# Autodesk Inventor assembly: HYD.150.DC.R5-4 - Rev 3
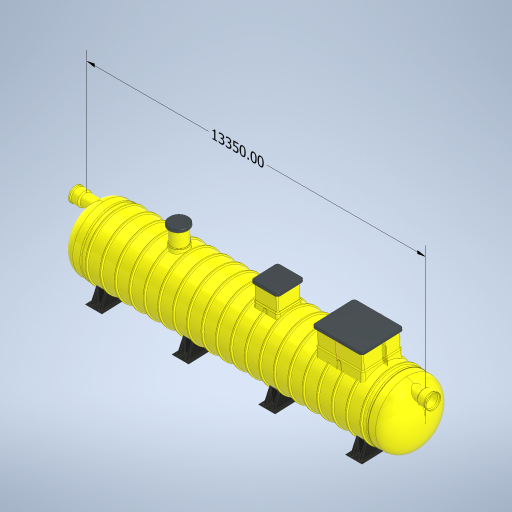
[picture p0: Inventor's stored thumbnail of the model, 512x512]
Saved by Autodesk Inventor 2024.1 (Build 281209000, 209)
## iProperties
Created: 2023-08
Part Number: HYD.150.DC.R5-4 - Rev 3
Document SubType Name: Assembly
Designer: macga
Author: macga
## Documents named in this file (48)
- D:\$ Protector Vault\Workspace\Automation Files\1. Protector Stardard Products\HydroProtectors\FAMILY\HYD.150 - Vernon\HYD.150.DC.R5-4 - Rev 3.iam
- D:\$ Protector Vault\Workspace\1. Protector Stardard Products\HydroProtectors\FAMILY\HORIZONTAL TANK - IPART\HORIZONTAL TANK - IPART.ipt
- D:\$ Protector Vault\Workspace\1. Protector Stardard Products\HydroProtectors\FAMILY\DOME - IPART\DOME - IPART.ipt
- D:\$ Protector Vault\Workspace\1. Protector Stardard Products\HydroProtectors\FAMILY\FOOT - IPART\FRP Foot - IPART.ipt
- D:\$ Protector Vault\Workspace\1. Protector Stardard Products\HydroProtectors\FAMILY\ACDTUBE - IPART\ACDTUBE - IPART.ipt
- D:\$ Protector Vault\Workspace\1. Protector Stardard Products\HydroProtectors\FAMILY\ACD FLOAT VALVE - IPART\ACD.FloatValve - IASSY.iam
- D:\$ Protector Vault\Workspace\1. Protector Stardard Products\HydroProtectors\FAMILY\COALESCER FILTER - IPART\CF-R5.iam
- D:\$ Protector Vault\Workspace\1. Protector Stardard Products\HydroProtectors\FAMILY\OUTLET ELBOW - IPART\OUTLET ELBOW - IPART.ipt
- D:\$ Protector Vault\Workspace\1. Protector Stardard Products\HydroProtectors\Coalescer Guide Rail.ipt
- D:\$ Protector Vault\Workspace\1. Protector Stardard Products\HydroProtectors\Upper Guide Rai Braket.ipt
- D:\$ Protector Vault\Workspace\1. Protector Stardard Products\Standard Components\Flanged Vent.ipt
- D:\$ Protector Vault\Workspace\1. Protector Stardard Products\HydroProtectors\HYD Oil Probe\Oil Probe Assembly.iam
- D:\$ Protector Vault\Workspace\1. Protector Stardard Products\HydroProtectors\FAMILY\ACD FLOAT VALVE - IPART\ACD.FloatValve - IASSY\ACD.FVALVE.450.ASSY.iam
- D:\$ Protector Vault\Workspace\1. Protector Stardard Products\Xtremeprotector\Vault\Chain.ipt
- D:\$ Protector Vault\Workspace\1. Protector Stardard Products\Xtremeprotector\Vault\Lifting Eye.ipt
- D:\$ Protector Vault\Workspace\1. Protector Stardard Products\HydroProtectors\FAMILY\HORIZONTAL TANK - IPART\HORIZONTAL TANK - IPART\WIN.HB.2500x11350L-12.ipt
- D:\$ Protector Vault\Workspace\1. Protector Stardard Products\HydroProtectors\FAMILY\DOME - IPART\DOME - IPART\SU.DOME.2500-12.ipt
- D:\$ Protector Vault\Workspace\1. Protector Stardard Products\HydroProtectors\FAMILY\HYD.BAFFLE - IPART\SU.BAFFLE.2500\SU.BAFFLE.2500.ipt
- D:\$ Protector Vault\Workspace\1. Protector Stardard Products\HydroProtectors\FAMILY\HYD.BAFFLE - IPART\SU.BAFFLE.2500.ipt
- D:\$ Protector Vault\Workspace\1. Protector Stardard Products\HydroProtectors\FAMILY\ACD Base - IPART\SU.ACDBASE.2500\SU.ACDBASE.2500-600ACDFV.ipt
- D:\$ Protector Vault\Workspace\1. Protector Stardard Products\HydroProtectors\FAMILY\ACD Base - IPART\SU.ACDBASE.2500.ipt
- D:\$ Protector Vault\Workspace\1. Protector Stardard Products\HydroProtectors\FAMILY\CF.BASE - IPART\CF BASE QUAD 2.0 - IPART.ipt
- D:\$ Protector Vault\Workspace\1. Protector Stardard Products\HydroProtectors\FAMILY\FOOT - IPART\FRP Foot - IPART\SU.HS.FOOT.2500.ipt
- D:\$ Protector Vault\Workspace\Manufacturing Drawings\ISO 4065 Pipe DN450x3.6xS63 - 2000.ipt
- D:\$ Protector Vault\Workspace\1. Protector Stardard Products\HydroProtectors\FAMILY\OUTLET ELBOW - IPART\OUTLET ELBOW - IPART\OutletPipeElbow.450D-100DCoupling.ipt
- D:\$ Protector Vault\Workspace\1. Protector Stardard Products\StormProtector\450 StormPro Pipe and Socket.ipt
- D:\$ Protector Vault\Workspace\1. Protector Stardard Products\HydroProtectors\FAMILY\ACDTUBE - IPART\ACDTUBE - IPART\ACDTUBE.600-2500.ipt
- D:\$ Protector Vault\Workspace\1. Protector Stardard Products\HydroProtectors\FAMILY\SU.900X900.ManwayRiserAdapter. - IPART\SU.900X900.ManwayRiserAdapator - IPART\SU.900x900ManwayRiserAdapter.2500.ipt
- D:\$ Protector Vault\Workspace\1. Protector Stardard Products\HydroProtectors\FAMILY\SU.900X900.ManwayRiserAdapter. - IPART\SU.900X900.ManwayRiserAdapator - IPART.ipt
- D:\$ Protector Vault\Workspace\1. Protector Stardard Products\Standard Components\900x900x600 Manway Riser.ipt
- D:\$ Protector Vault\Workspace\1. Protector Stardard Products\Standard Components\900x900 Manway Cover ST.ipt
- D:\$ Protector Vault\Workspace\1. Protector Stardard Products\Standard Components\900x900 Manway Cover ST\900x900 Manway Cover Class D ST-02.ipt
- D:\$ Protector Vault\Workspace\1. Protector Stardard Products\Xtremeprotector\Vault\Chain\Chain-44.ipt
- D:\$ Protector Vault\Workspace\1. Protector Stardard Products\StormProtector\450 StormPro Inlet Elbow.ipt
- D:\$ Protector Vault\Workspace\1. Protector Stardard Products\HydroProtectors\FAMILY\CF.BASE - IPART\CF BASE QUAD 2.0 - IPART\SU.CFBASE.2500.B2.4-R6-OP.450.ipt
- D:\$ Protector Vault\Workspace\1. Protector Stardard Products\Standard Components\1500x1800 Manway Adaptor\SU.1500x1800ManwayRiserAdaptor.2500.ipt
- D:\$ Protector Vault\Workspace\1. Protector Stardard Products\Standard Components\1500x1800 Manway Adaptor.ipt
- D:\$ Protector Vault\Workspace\1. Protector Stardard Products\Standard Components\1500x1800x600 Manway Riser.ipt
- D:\$ Protector Vault\Workspace\1. Protector Stardard Products\Standard Components\1500x1800 Manway Cover ST\1500x1800 Manway Cover Class D ST-02.ipt
- D:\$ Protector Vault\Workspace\1. Protector Stardard Products\Standard Components\1500x1800 Manway Cover ST.ipt
- D:\$ Protector Vault\Workspace\1. Protector Stardard Products\HydroProtectors\FAMILY\Coalescer Guide Rail-0121.ipt
- D:\$ Protector Vault\Workspace\1. Protector Stardard Products\HydroProtectors\FAMILY\Coalescer Guide Rail-0122.ipt
- D:\$ Protector Vault\Workspace\1. Protector Stardard Products\HydroProtectors\FAMILY\COALESCER FILTER - IPART\CF-R5_MIR.iam
- D:\$ Protector Vault\Workspace\1. Protector Stardard Products\Xtremeprotector\Vault\Lifting Eye_MIR1.ipt
- D:\$ Protector Vault\Workspace\1. Protector Stardard Products\HydroProtectors\Upper Guide Rai Braket_MIR1.ipt
- D:\$ Protector Vault\Workspace\1. Protector Stardard Products\600 Dia Adaptor, Riser, Cover Assy - 2500\600 Dia Adaptor, Riser, Class D Cover Assy - 1850.iam
- D:\$ Protector Vault\Workspace\1. Protector Stardard Products\600 Dia Adaptor, Riser, Cover Assy - 2500.iam
- D:\$ Protector Vault\Workspace\1. Protector Stardard Products\Trade Waste Sampling Point Assembly 450.iam
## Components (47 placed, 31 different names)
1. WIN.HB.2500x11350L-12:1
2. SU.DOME.2500-12:1 — Mate:1, Mate:3, Mate:78, Mate:93, Flush:127, Angle:5, Angle:11
3. 450 StormPro Inlet Elbow:1 — Flush:127, Angle:5
4. SU.DOME.2500-12:2 — Mate:2, Mate:4, Mate:94, Angle:4
5. SU.HS.FOOT.2500:1 — Mate:74, Mate:75, Flush:128, Angle:7
6. SU.HS.FOOT.2500:2 — Mate:76, Mate:77, Flush:131, Angle:10
7. SU.HS.FOOT.2500:3 — Mate:149, Mate:150, Flush:130, Angle:9
8. SU.HS.FOOT.2500:4 — Mate:147, Mate:148, Flush:129, Angle:8
9. SU.BAFFLE.2500:1 — Mate:78, Mate:79, Flush:10, Mate:95, Angle:4
10. SU.ACDBASE.2500-600ACDFV:1 — Mate:11, Mate:13, Mate:14, Mate:79, Mate:95, Angle:3, Mate:100, Flush:103, Flush:116
11. ACDTUBE.600-2500:1 — Mate:13, Mate:14, Mate:96, Mate:97, Flush:103
12. ACD.FVALVE.450.ASSY:1 [sub-assembly] — Mate:96, Mate:97
13. SU.CFBASE.2500.B2.4-R6-OP.450:1 — Mate:16, Flush:132, Mate:153, Mate:154, Mate:155, Mate:171, Mate:172
14. CF-R5:1 [sub-assembly] — Mate:153, Mate:154, Flush:134, Mate:157, Tangent:126
15. CF-R5:2 [sub-assembly] — Mate:86, Tangent:4, Mate:155, Flush:134
16. ISO 4065 Pipe DN450x3.6xS63 - 2000:1 — Mate:171, Mate:172, Mate:173, Mate:174
17. OutletPipeElbow.450D-100DCoupling:2 — Mate:173, Mate:174, Mate:175, Mate:176
18. 450 StormPro Pipe and Socket:1 — Mate:175, Mate:176, Mate:181, Mate:182
19. 900x900x600 Manway Riser:1 — Mate:120, Mate:121, Mate:122, Mate:123, Flush:117, Flush:118
20. 900x900 Manway Cover Class D ST-02:1 — Mate:123, Flush:117, Flush:118, Flush:138
21. Flanged Vent:3 — Mate:71, Mate:72
22. Flanged Vent:4 — Mate:170
23. SU.900x900ManwayRiserAdapter.2500:1 — Mate:70, Mate:71, Mate:72, Flush:116, Mate:120, Mate:121, Mate:122, Angle:6
24. Oil Probe Assembly:1 [sub-assembly] — Mate:179, Angle:14, Mate:180
25. Chain-44:1 — Mate:157, Tangent:126, Tangent:127
26. Chain-44:2 — Mate:86, Tangent:4, Tangent:128
27. Lifting Eye:1 — Mate:138, Tangent:127, Mate:160
28. Lifting Eye:2 — Tangent:128, Mate:161
29. Coalescer Guide Rail-0121:1 — Mate:62, Mate:63, Flush:5, Angle:13, Mate:158
30. Coalescer Guide Rail-0122:2 — Mate:64, Mate:65, Flush:6, Mate:159
31. Upper Guide Rai Braket:1 — Mate:62, Mate:63, Flush:5, Mate:160
32. Upper Guide Rai Braket:2 — Mate:64, Mate:65, Flush:6, Mate:161
33. SU.1500x1800ManwayRiserAdaptor.2500:1 — Flush:132, Flush:133, Angle:13, Mate:170
34. 1500x1800x600 Manway Riser:1 — Mate:138, Flush:133, Mate:158, Mate:159
35. 1500x1800 Manway Cover Class D ST-02:1 — Angle:15
36. CF-R5_MIR:1 [sub-assembly] — Flush:135, Tangent:129, Mate:166
37. CF-R5_MIR:2 [sub-assembly] — Flush:135, Mate:167, Tangent:130
38. Chain-44:3 — Tangent:129, Mate:166, Tangent:131
39. Chain-44:4 — Mate:167, Tangent:130, Tangent:132
40. Lifting Eye_MIR1:1 — Mate:168, Tangent:131
41. Lifting Eye_MIR1:2 — Mate:169, Tangent:132
42. Coalescer Guide Rail-0121:3 — Flush:136, Mate:162, Mate:163
43. Coalescer Guide Rail-0122:4 — Flush:137, Mate:164, Mate:165
44. Upper Guide Rai Braket_MIR1:1 — Flush:136, Mate:162, Mate:163, Mate:168
45. Upper Guide Rai Braket_MIR1:2 — Flush:137, Mate:164, Mate:165, Mate:169
46. 600 Dia Adaptor, Riser, Class D Cover Assy - 1850:1 [sub-assembly] — Mate:177, Flush:138, Mate:178, Mate:179, Angle:14, Mate:180
47. Trade Waste Sampling Point Assembly 450:1 [sub-assembly] — Mate:181, Angle:15, Mate:182
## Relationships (105: Mate 66, Flush 19, Angle 12, Tangent 8)
- Mate:1: SU.DOME.2500-12:1
- Mate:2: SU.DOME.2500-12:2
- Mate:3: SU.DOME.2500-12:1
- Mate:4: SU.DOME.2500-12:2
- Mate:11: SU.ACDBASE.2500-600ACDFV:1
- Mate:13: SU.ACDBASE.2500-600ACDFV:1 ↔ ACDTUBE.600-2500:1
- Mate:14: SU.ACDBASE.2500-600ACDFV:1 ↔ ACDTUBE.600-2500:1
- Mate:16: SU.CFBASE.2500.B2.4-R6-OP.450:1
- Mate:62: Coalescer Guide Rail-0121:1 ↔ Upper Guide Rai Braket:1
- Mate:63: Coalescer Guide Rail-0121:1 ↔ Upper Guide Rai Braket:1
- Flush:5: Coalescer Guide Rail-0121:1 ↔ Upper Guide Rai Braket:1
- Mate:64: Coalescer Guide Rail-0122:2 ↔ Upper Guide Rai Braket:2
- Mate:65: Coalescer Guide Rail-0122:2 ↔ Upper Guide Rai Braket:2
- Flush:6: Coalescer Guide Rail-0122:2 ↔ Upper Guide Rai Braket:2
- Mate:70: SU.900x900ManwayRiserAdapter.2500:1
- Mate:71: Flanged Vent:3 ↔ SU.900x900ManwayRiserAdapter.2500:1
- Mate:72: Flanged Vent:3 ↔ SU.900x900ManwayRiserAdapter.2500:1
- Mate:74: SU.HS.FOOT.2500:1
- Mate:75: SU.HS.FOOT.2500:1
- Mate:76: SU.HS.FOOT.2500:2
- Mate:77: SU.HS.FOOT.2500:2
- Mate:78: SU.DOME.2500-12:1 ↔ SU.BAFFLE.2500:1
- Mate:79: SU.BAFFLE.2500:1 ↔ SU.ACDBASE.2500-600ACDFV:1
- Mate:86: CF-R5:2 ↔ Chain-44:2
- Tangent:4: CF-R5:2 ↔ Chain-44:2
- Mate:93: SU.DOME.2500-12:1
- Mate:94: SU.DOME.2500-12:2
- Flush:10: SU.BAFFLE.2500:1
- Mate:95: SU.BAFFLE.2500:1 ↔ SU.ACDBASE.2500-600ACDFV:1
- Mate:96: ACDTUBE.600-2500:1 ↔ ACD.FVALVE.450.ASSY:1
- Mate:97: ACDTUBE.600-2500:1 ↔ ACD.FVALVE.450.ASSY:1
- Angle:3: SU.ACDBASE.2500-600ACDFV:1
- Mate:100: SU.ACDBASE.2500-600ACDFV:1
- Flush:103: SU.ACDBASE.2500-600ACDFV:1 ↔ ACDTUBE.600-2500:1
- Angle:4: SU.DOME.2500-12:2 ↔ SU.BAFFLE.2500:1
- Flush:116: SU.ACDBASE.2500-600ACDFV:1 ↔ SU.900x900ManwayRiserAdapter.2500:1
- Mate:120: 900x900x600 Manway Riser:1 ↔ SU.900x900ManwayRiserAdapter.2500:1
- Mate:121: 900x900x600 Manway Riser:1 ↔ SU.900x900ManwayRiserAdapter.2500:1
- Mate:122: 900x900x600 Manway Riser:1 ↔ SU.900x900ManwayRiserAdapter.2500:1
- Mate:123: 900x900x600 Manway Riser:1 ↔ 900x900 Manway Cover Class D ST-02:1
- Flush:117: 900x900x600 Manway Riser:1 ↔ 900x900 Manway Cover Class D ST-02:1
- Flush:118: 900x900x600 Manway Riser:1 ↔ 900x900 Manway Cover Class D ST-02:1
- Mate:138: Lifting Eye:1 ↔ 1500x1800x600 Manway Riser:1
- Mate:147: SU.HS.FOOT.2500:4
- Mate:148: SU.HS.FOOT.2500:4
- Mate:149: SU.HS.FOOT.2500:3
- Mate:150: SU.HS.FOOT.2500:3
- Flush:127: SU.DOME.2500-12:1 ↔ 450 StormPro Inlet Elbow:1
- Angle:5: SU.DOME.2500-12:1 ↔ 450 StormPro Inlet Elbow:1
- Angle:6: SU.900x900ManwayRiserAdapter.2500:1
- Flush:128: SU.HS.FOOT.2500:1
- Angle:7: SU.HS.FOOT.2500:1
- Flush:129: SU.HS.FOOT.2500:4
- Angle:8: SU.HS.FOOT.2500:4
- Flush:130: SU.HS.FOOT.2500:3
- Angle:9: SU.HS.FOOT.2500:3
- Flush:131: SU.HS.FOOT.2500:2
- Angle:10: SU.HS.FOOT.2500:2
- Angle:11: SU.DOME.2500-12:1
- Flush:132: SU.CFBASE.2500.B2.4-R6-OP.450:1 ↔ SU.1500x1800ManwayRiserAdaptor.2500:1
- Flush:133: SU.1500x1800ManwayRiserAdaptor.2500:1 ↔ 1500x1800x600 Manway Riser:1
- Mate:153: SU.CFBASE.2500.B2.4-R6-OP.450:1 ↔ CF-R5:1
- Mate:154: SU.CFBASE.2500.B2.4-R6-OP.450:1 ↔ CF-R5:1
- Mate:155: SU.CFBASE.2500.B2.4-R6-OP.450:1 ↔ CF-R5:2
- Flush:134: CF-R5:1 ↔ CF-R5:2
- Mate:157: CF-R5:1 ↔ Chain-44:1
- Tangent:126: CF-R5:1 ↔ Chain-44:1
- Angle:13: Coalescer Guide Rail-0121:1 ↔ SU.1500x1800ManwayRiserAdaptor.2500:1
- Mate:158: Coalescer Guide Rail-0121:1 ↔ 1500x1800x600 Manway Riser:1
- Tangent:127: Chain-44:1 ↔ Lifting Eye:1
- Mate:159: Coalescer Guide Rail-0122:2 ↔ 1500x1800x600 Manway Riser:1
- Tangent:128: Chain-44:2 ↔ Lifting Eye:2
- Mate:160: Lifting Eye:1 ↔ Upper Guide Rai Braket:1
- Mate:161: Lifting Eye:2 ↔ Upper Guide Rai Braket:2
- Flush:135: CF-R5_MIR:1 ↔ CF-R5_MIR:2
- Flush:136: Coalescer Guide Rail-0121:3 ↔ Upper Guide Rai Braket_MIR1:1
- Mate:162: Coalescer Guide Rail-0121:3 ↔ Upper Guide Rai Braket_MIR1:1
- Mate:163: Coalescer Guide Rail-0121:3 ↔ Upper Guide Rai Braket_MIR1:1
- Flush:137: Coalescer Guide Rail-0122:4 ↔ Upper Guide Rai Braket_MIR1:2
- Mate:164: Coalescer Guide Rail-0122:4 ↔ Upper Guide Rai Braket_MIR1:2
- Mate:165: Coalescer Guide Rail-0122:4 ↔ Upper Guide Rai Braket_MIR1:2
- Tangent:129: CF-R5_MIR:1 ↔ Chain-44:3
- Mate:166: CF-R5_MIR:1 ↔ Chain-44:3
- Mate:167: CF-R5_MIR:2 ↔ Chain-44:4
- Tangent:130: CF-R5_MIR:2 ↔ Chain-44:4
- Mate:168: Lifting Eye_MIR1:1 ↔ Upper Guide Rai Braket_MIR1:1
- Tangent:131: Chain-44:3 ↔ Lifting Eye_MIR1:1
- Mate:169: Lifting Eye_MIR1:2 ↔ Upper Guide Rai Braket_MIR1:2
- Tangent:132: Chain-44:4 ↔ Lifting Eye_MIR1:2
- Mate:170: Flanged Vent:4 ↔ SU.1500x1800ManwayRiserAdaptor.2500:1
- Mate:171: SU.CFBASE.2500.B2.4-R6-OP.450:1 ↔ ISO 4065 Pipe DN450x3.6xS63 - 2000:1
- Mate:172: SU.CFBASE.2500.B2.4-R6-OP.450:1 ↔ ISO 4065 Pipe DN450x3.6xS63 - 2000:1
- Mate:173: ISO 4065 Pipe DN450x3.6xS63 - 2000:1 ↔ OutletPipeElbow.450D-100DCoupling:2
- Mate:174: ISO 4065 Pipe DN450x3.6xS63 - 2000:1 ↔ OutletPipeElbow.450D-100DCoupling:2
- Mate:175: OutletPipeElbow.450D-100DCoupling:2 ↔ 450 StormPro Pipe and Socket:1
- Mate:176: OutletPipeElbow.450D-100DCoupling:2 ↔ 450 StormPro Pipe and Socket:1
- Mate:177: 600 Dia Adaptor, Riser, Class D Cover Assy - 1850:1
- Flush:138: 900x900 Manway Cover Class D ST-02:1 ↔ 600 Dia Adaptor, Riser, Class D Cover Assy - 1850:1
- Mate:178: 600 Dia Adaptor, Riser, Class D Cover Assy - 1850:1
- Mate:179: Oil Probe Assembly:1 ↔ 600 Dia Adaptor, Riser, Class D Cover Assy - 1850:1
- Angle:14: Oil Probe Assembly:1 ↔ 600 Dia Adaptor, Riser, Class D Cover Assy - 1850:1
- Mate:180: Oil Probe Assembly:1 ↔ 600 Dia Adaptor, Riser, Class D Cover Assy - 1850:1
- Mate:181: 450 StormPro Pipe and Socket:1 ↔ Trade Waste Sampling Point Assembly 450:1
- Angle:15: 1500x1800 Manway Cover Class D ST-02:1 ↔ Trade Waste Sampling Point Assembly 450:1
- Mate:182: 450 StormPro Pipe and Socket:1 ↔ Trade Waste Sampling Point Assembly 450:1
